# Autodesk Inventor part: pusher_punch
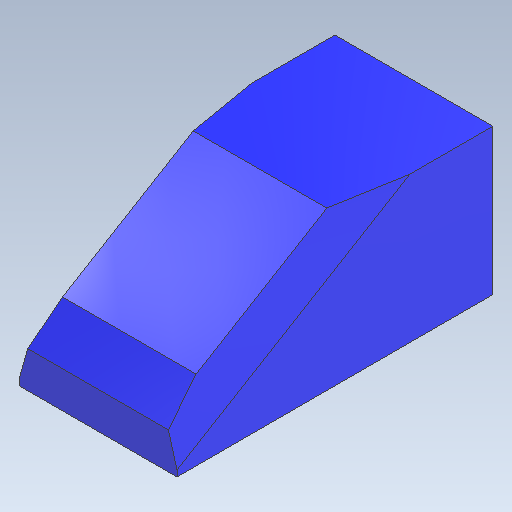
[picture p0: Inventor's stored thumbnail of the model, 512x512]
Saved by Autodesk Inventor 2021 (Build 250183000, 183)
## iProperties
Created: 2026-10
Part Number: pusher_punch
Material: Generic
Document SubType Name: Modeling
Designer: alolo
Density: 1 g/cm^3
Appearance: Default
Author: alolo
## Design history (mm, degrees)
sketch "Sketch1"
  geometry: L1 (0, 0)-(65, 0); L2 (65, 0)-(65, 80); L3 (65, 80)-(0, 80); L4 (0, 80)-(0, 0)
  constraints: 8 end point, 2 parallel, 1 horizontal, 1 perpendicular
  dimensions: "d0" = 65 distance of L3.end L2.end (= slide_width); "d1" = 80 distance of L2.end L1.end
extrude "Extrusion1" new body sketch "Sketch1" distance "d2" = 130; taper "d3" = 0 deg
sketch "Sketch2"
  geometry: L1 (0, 0)-(-65, 0) reference; L2 (-38.5, 0)-(-26.5, 0); L3 (-26.5, 0)-(-26.5, 15); L4 (-26.5, 15)-(-38.5, 15); L5 (-38.5, 15)-(-38.5, 0); 3 further points
  constraints: 8 end point, 2 midpoint, 2 parallel, 1 coincident, 1 horizontal, 1 perpendicular, 1 point on line
  dimensions: "d19" = 12 distance of L4.end L3.end; "d20" = 15 distance of L2.end L3.end
extrude "Extrusion2" cut sketch "Sketch2" distance "d21" = 40; taper "d22" = 0 deg
chamfer "Chamfer6" distance "d23" = 60; stored, may be unused: second distance "d24" = 100, angle "d25" = 45 deg
chamfer "Chamfer7" distance "d26" = 15; stored, may be unused: second distance "d27" = 5, angle "d28" = 45 deg
chamfer "Chamfer8" distance "d29" = 10; stored, may be unused: second distance "d30" = 2, angle "d31" = 45 deg
chamfer "Chamfer10" distance "d35" = 5; stored, may be unused: second distance "d36" = 15, angle "d37" = 45 deg
chamfer "Chamfer11" distance "d38" = 5; stored, may be unused: second distance "d39" = 15, angle "d40" = 45 deg
sketch "Sketch3"
  geometry: L1 (-65, 0)-(-65, 80) reference; L2 (0, 80)-(0, 0) reference; L3 (-65, 80)-(0, 80); L4 (0, 80)-(0, 60); L5 (0, 60)-(-65, 60); L6 (-65, 60)-(-65, 80); 2 further points
  constraints: 8 end point, 2 parallel, 1 horizontal, 1 perpendicular, 1 point on line
  dimensions: "d41" = 20 distance of L3.end L4.end
extrude "Extrusion3" cut sketch "Sketch3" stored distance "d42" = 10; taper "d43" = 0 deg
body "Solid1"
other parameters: "slide_length" = 195 [user parameter], "slide_angle" = 7 deg [user parameter], "slide_width" = 65 [user parameter; used in 1 equation term], "wood_thickness" = 5 [user parameter], "aclyric_thickness" = 6 [user parameter]
